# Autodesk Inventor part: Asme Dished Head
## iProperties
Author: RT
Shininess: 64.0
Angle Display Precision: 2
Document Length Units: 11272
Document Angle Units: 11286
Document Time Units: 11279
Document Mass Units: 11290
Document Length Units Precision: 3
Document Angle Units Precision: 2
Compacted: False
PropertySet Name: _Private Model Information
Created: 2004-02
Part Number: Asme Dished Head
Document SubType Name: Modeling
Designer: RT
Control State: 0
Master: False
Checked Out: False
PropertySet Name: Design Tracking Control
Density: 0.0
Volumn: 0.0
Area: 0.0
PropertySet Name: Model Information
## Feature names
1. Revolution1
